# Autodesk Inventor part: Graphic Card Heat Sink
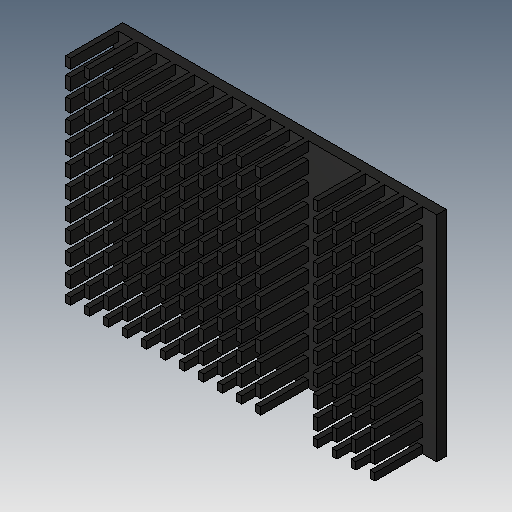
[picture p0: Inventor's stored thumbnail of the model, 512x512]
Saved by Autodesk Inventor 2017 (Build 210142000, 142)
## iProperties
Created: 2005-12
Part Number: Graphic Card Heat Sink
Material: Generic
Document SubType Name: Modeling
Designer: DanielSeverino
Density: 1 g/cm^3
Appearance: Default
Author: DanielSeverino
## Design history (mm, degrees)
feature "Solid1"
body "Solid2"
